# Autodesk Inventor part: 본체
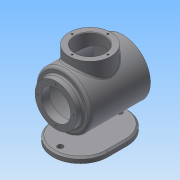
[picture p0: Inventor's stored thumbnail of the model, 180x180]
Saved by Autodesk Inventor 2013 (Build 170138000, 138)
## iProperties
Created: 2016-04
Part Number: 본체
Material: Generic
Document SubType Name: Modeling
Designer: Administrator
Density: 1 g/cm^3
Author: Administrator
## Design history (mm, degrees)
sketch "스케치2"
  geometry: C1 r 50 at (0, 0); 1 further point
  constraints: 1 centre point, 1 coincident
  dimensions: "d10" = 100 diameter of C1
extrude "돌출2" new body sketch "스케치2" distance "d12" = 110; taper "d13" = 0 deg
sketch "스케치3"
  geometry: C1 r 50 at (0, 0) reference; C2 r 38 at (0, 0)
  constraints: 1 centre point, 1 coincident
  dimensions: "d14" = 76 diameter of C2
extrude "돌출3" join sketch "스케치3" distance "d16" = 12; taper "d17" = 0 deg
sketch "스케치4"
  geometry: C1 r 38 at (0, 0) reference; C2 r 27 at (0, 0)
  constraints: 1 centre point, 1 coincident
  dimensions: "d18" = 54 diameter of C2
extrude "돌출4" cut sketch "스케치4" distance "d20" = 15; taper "d21" = 0 deg
node "작업 평면1"
sketch "스케치6"
  geometry: C1 r 27 at (0, 0) reference; C2 r 47 at (0, 0)
  constraints: 1 centre point, 1 coincident
  dimensions: "d23" = 94 diameter of C2
extrude "돌출5" cut sketch "스케치6" distance "d25" = 99.5; taper "d26" = 0 deg
node "작업 평면5"
  node "작업 평면4"
sketch "스케치8"
  geometry: L1 (50, 110)-(-50, 110) reference; C1 r 38 at (0, 60); 1 further point
  constraints: 1 centre point
  dimensions: "d30" = 50 distance from line of L1 C1.centre; "d31" = 0 horizontal distance of point (0, 0) C1.centre; "d32" = 76 diameter of C1
extrude "돌출6" join sketch "스케치8" stored distance "d33" = 99.5; taper "d34" = 0 deg
sketch "스케치9"
  geometry: C1 r 38 at (0, 0) reference; C2 r 27 at (0, 0); 1 further point
  constraints: 1 centre point, 1 coincident
  dimensions: "d35" = 54 diameter of C2
extrude "돌출7" cut sketch "스케치9" stored distance "d37" = 99.5; taper "d38" = 0 deg
sketch "스케치10" dims "d39" = 65
  geometry: C1 r 27 at (0, 0) reference; C2 r 38 at (0, 0) reference; C3 r 2 at (0, 32.5); 2 further points
  constraints: 1 centre point, 1 coincident, 1 vertical alignment, 2 other
  dimensions: "d41" = 0 horizontal distance of C1.centre C3.centre; "d42" = 4 diameter of C3
hole "구멍1" sketch "스케치10" at (0, 32.5) diameter "d43" = 3.242; stored, may be unused: countersink angle "d47" = 90 deg, drill point angle "d49" = 118 deg; dims "d44" = 8, "d45" = 4, "d46" = 2, "d48" = 10
chamfer "모따기1" distance "d53" = 1; stored, may be unused: second distance "d54" = 2, angle "d55" = 45 deg
sketch "스케치11" dims "d56" = 65
  geometry: C1 r 27 at (0, 0) reference; C2 r 38 at (0, 0) reference; C3 r 2 at (0, 32.5); 1 further point
  constraints: 1 centre point, 1 coincident, 1 vertical alignment, 2 other
  dimensions: "d58" = 0 horizontal distance of C1.centre C3.centre; "d59" = 4 diameter of C3
hole "구멍2" sketch "스케치11" at (0, 32.5) diameter "d60" = 3.242; stored, may be unused: countersink angle "d64" = 90 deg, drill point angle "d66" = 118 deg; dims "d61" = 8, "d62" = 4, "d63" = 2, "d65" = 10
node "작업 평면6"
fillet "모깎기1" dims "d71" = 3
fillet "모깎기2" dims "d72" = 5
fillet "모깎기3" dims "d73" = 3
fillet "모깎기4" dims "d74" = 2
node "작업 평면7"
sketch "스케치13"
  geometry: L1 (50, 127.5)-(-50, 127.5); L2 (-50, 127.5)-(-50, -7.5); L3 (-50, -7.5)-(50, -7.5); L4 (50, 0)-(50, 105) reference; L5 (-50, 0)-(-50, 105) reference; L6 (50, 52.5)-(-50, 52.5); L7 (50, 127.5)-(50, -7.5); 1 further point
  constraints: 10 end point, 2 midpoint, 1 collinear, 1 horizontal, 1 parallel, 1 perpendicular
  dimensions: "d80" = 135 distance of L3.end L1.start; "d82" = 100 distance of L2.end L3.end; "d84" = 50 horizontal distance of L2.end point (0, 0); "d85" = 75 distance between parallel lines of L1 L6
extrude "돌출8" join sketch "스케치13" distance "d86" = 10; taper "d87" = 0 deg
fillet "모깎기5" dims "d88" = 50
sketch "스케치14"
  geometry: L1 (-50, -42.5)-(-50, -77.5) reference; L2 (50, -77.5)-(50, -42.5) reference; L3 (-50, -60)-(50, -60); C1 r 5 at (0, -6); C2 r 5 at (0, -114); A1 r 50 centre (0, -77.5) between (-50, -77.5) and (50, -77.5) reference; 1 further point
  constraints: 2 centre point, 2 end point, 2 midpoint
  dimensions: "d89" = 108 distance of C2.centre C1.centre; "d93" = 10 diameter of C2; "d94" = 54 distance from line of L3 C1.centre; "d95" = 0 horizontal distance of point (0, 0) C1.centre; "d96" = 0 horizontal distance of A1.centre C2.centre; "d97" = 10 diameter of C1
extrude "돌출9" cut sketch "스케치14" stored distance "d98" = 10; taper "d99" = 0 deg
chamfer "모따기2" distance "d100" = 3; stored, may be unused: second distance "d101" = 2, angle "d102" = 45 deg
node "작업 평면8"
node "솔리드2"
pattern_circular "원형 패턴1" dims angle "d51" = 360 deg
pattern_circular "원형 패턴2" dims angle "d68" = 360 deg
other parameters: "d22" = 72, "d28" = -79, "d29" = 144, "d70" = -79, "d75" = -79
